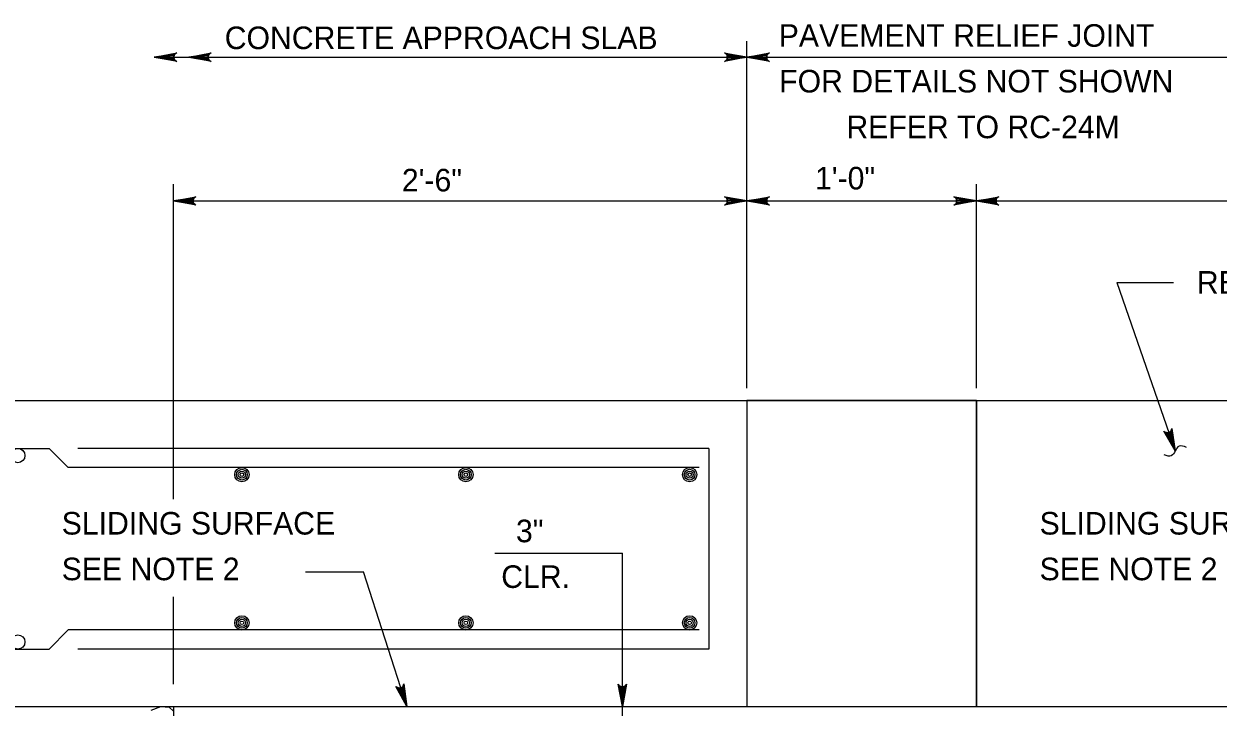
# Model space of a CAD drawing. Extents: x 638079 to 640019, y 297691 to 298879.
# Drawn here: x 639245.9 to 639404.5, y 298536.4 to 298627.2 of the extents above; entities that cross this region are included whole.
import ezdxf

# ---------------------------------------------------------------- set-up
doc = ezdxf.new("R2010")
doc.units = 0
doc.layers.add('1', color=7, linetype='Continuous')

msp = doc.modelspace()

# ---------------------------------------------------------------- linework, layer by layer
at = {"layer": '1'}
for p, q in [((639341.94, 298578.79), (639341.94, 298624.88)), ((639263.19, 298622.76), (639341.94, 298622.76)), ((639341.94, 298622.76), (639417.03, 298622.76)), ((639265.74, 298564.03), (639265.74, 298605.88)), ((639372.42, 298578.79), (639372.42, 298605.88)), ((639265.74, 298603.66), (639448.62, 298603.66)), ((639391.09, 298592.81), (639398.61, 298592.81)), ((639391.09, 298592.81), (639398.84, 298570.43)), ((639199.6, 298577.12), (639341.94, 298577.12)), ((639341.94, 298577.12), (639523.91, 298577.12)), ((639341.94, 298577.12), (639341.94, 298536.48)), ((639372.42, 298577.12), (639372.42, 298536.48)), ((639199.6, 298570.77), (639249.23, 298570.77)), ((639251.77, 298568.23), (639249.23, 298570.77)), ((639336.86, 298570.77), (639253.04, 298570.77)), ((639336.86, 298570.77), (639336.86, 298544.1)), ((639335.59, 298568.23), (639251.77, 298568.23)), ((639308.44, 298556.84), (639325.38, 298556.84)), ((639325.38, 298522.44), (639325.38, 298556.84)), ((639283.3, 298554.39), (639291.01, 298554.39)), ((639296.74, 298536.48), (639291.01, 298554.39)), ((639265.74, 298539.46), (639265.74, 298551.03)), ((639251.77, 298546.64), (639249.23, 298544.1)), ((639335.59, 298546.64), (639251.77, 298546.64)), ((639199.6, 298544.1), (639249.23, 298544.1)), ((639336.86, 298544.1), (639253.04, 298544.1)), ((639199.6, 298536.48), (639341.94, 298536.48)), ((639265.74, 298536.48), (639448.62, 298536.48)), ((639265.74, 298536.48), (639265.74, 298506))]:
    msp.add_line(p, q, dxfattribs=at)
for points in [[(639263.19, 298622.76), (639266.17, 298623.32), (639266.05, 298623.24), (639265.94, 298623.16), (639265.88, 298623.06), (639265.82, 298622.96), (639265.8, 298622.86), (639265.79, 298622.76), (639265.8, 298622.66), (639265.82, 298622.56), (639265.88, 298622.46), (639265.94, 298622.36), (639266.05, 298622.28), (639266.17, 298622.2), (639263.19, 298622.76), (639266.05, 298622.28), (639265.94, 298622.36), (639263.19, 298622.76), (639265.88, 298622.46), (639265.82, 298622.56), (639263.19, 298622.76), (639265.8, 298622.66), (639265.79, 298622.76), (639263.19, 298622.76), (639265.8, 298622.86), (639265.82, 298622.96), (639263.19, 298622.76), (639265.88, 298623.06), (639265.94, 298623.16), (639263.19, 298622.76), (639266.05, 298623.24)], [(639267.76, 298622.76), (639270.74, 298623.32), (639270.63, 298623.24), (639270.51, 298623.16), (639270.45, 298623.06), (639270.39, 298622.96), (639270.37, 298622.86), (639270.36, 298622.76), (639270.37, 298622.66), (639270.39, 298622.56), (639270.45, 298622.46), (639270.51, 298622.36), (639270.63, 298622.28), (639270.74, 298622.2), (639267.76, 298622.76), (639270.63, 298622.28), (639270.51, 298622.36), (639267.76, 298622.76), (639270.45, 298622.46), (639270.39, 298622.56), (639267.76, 298622.76), (639270.37, 298622.66), (639270.36, 298622.76), (639267.76, 298622.76), (639270.37, 298622.86), (639270.39, 298622.96), (639267.76, 298622.76), (639270.45, 298623.06), (639270.51, 298623.16), (639267.76, 298622.76), (639270.63, 298623.24)], [(639341.94, 298622.76), (639338.96, 298622.2), (639339.07, 298622.28), (639339.19, 298622.36), (639339.25, 298622.46), (639339.31, 298622.56), (639339.32, 298622.66), (639339.34, 298622.76), (639339.32, 298622.86), (639339.31, 298622.96), (639339.25, 298623.06), (639339.19, 298623.16), (639339.07, 298623.24), (639338.96, 298623.32), (639341.94, 298622.76), (639339.07, 298623.24), (639339.19, 298623.16), (639341.94, 298622.76), (639339.25, 298623.06), (639339.31, 298622.96), (639341.94, 298622.76), (639339.32, 298622.86), (639339.34, 298622.76), (639341.94, 298622.76), (639339.32, 298622.66), (639339.31, 298622.56), (639341.94, 298622.76), (639339.25, 298622.46), (639339.19, 298622.36), (639341.94, 298622.76), (639339.07, 298622.28)], [(639341.94, 298622.76), (639344.92, 298623.32), (639344.81, 298623.24), (639344.69, 298623.16), (639344.63, 298623.06), (639344.57, 298622.96), (639344.56, 298622.86), (639344.54, 298622.76), (639344.56, 298622.66), (639344.57, 298622.56), (639344.63, 298622.46), (639344.69, 298622.36), (639344.81, 298622.28), (639344.92, 298622.2), (639341.94, 298622.76), (639344.81, 298622.28), (639344.69, 298622.36), (639341.94, 298622.76), (639344.63, 298622.46), (639344.57, 298622.56), (639341.94, 298622.76), (639344.56, 298622.66), (639344.54, 298622.76), (639341.94, 298622.76), (639344.56, 298622.86), (639344.57, 298622.96), (639341.94, 298622.76), (639344.63, 298623.06), (639344.69, 298623.16), (639341.94, 298622.76), (639344.81, 298623.24)], [(639265.74, 298603.66), (639268.72, 298604.22), (639268.61, 298604.14), (639268.49, 298604.06), (639268.43, 298603.96), (639268.37, 298603.86), (639268.36, 298603.76), (639268.34, 298603.66), (639268.36, 298603.56), (639268.37, 298603.46), (639268.43, 298603.36), (639268.49, 298603.26), (639268.61, 298603.18), (639268.72, 298603.1), (639265.74, 298603.66), (639268.61, 298603.18), (639268.49, 298603.26), (639265.74, 298603.66), (639268.43, 298603.36), (639268.37, 298603.46), (639265.74, 298603.66), (639268.36, 298603.56), (639268.34, 298603.66), (639265.74, 298603.66), (639268.36, 298603.76), (639268.37, 298603.86), (639265.74, 298603.66), (639268.43, 298603.96), (639268.49, 298604.06), (639265.74, 298603.66), (639268.61, 298604.14)], [(639341.94, 298603.66), (639338.96, 298603.1), (639339.07, 298603.18), (639339.19, 298603.26), (639339.25, 298603.36), (639339.31, 298603.46), (639339.32, 298603.56), (639339.34, 298603.66), (639339.32, 298603.76), (639339.31, 298603.86), (639339.25, 298603.96), (639339.19, 298604.06), (639339.07, 298604.14), (639338.96, 298604.22), (639341.94, 298603.66), (639339.07, 298604.14), (639339.19, 298604.06), (639341.94, 298603.66), (639339.25, 298603.96), (639339.31, 298603.86), (639341.94, 298603.66), (639339.32, 298603.76), (639339.34, 298603.66), (639341.94, 298603.66), (639339.32, 298603.56), (639339.31, 298603.46), (639341.94, 298603.66), (639339.25, 298603.36), (639339.19, 298603.26), (639341.94, 298603.66), (639339.07, 298603.18)], [(639341.94, 298603.66), (639344.92, 298604.22), (639344.81, 298604.14), (639344.69, 298604.06), (639344.63, 298603.96), (639344.57, 298603.86), (639344.56, 298603.76), (639344.54, 298603.66), (639344.56, 298603.56), (639344.57, 298603.46), (639344.63, 298603.36), (639344.69, 298603.26), (639344.81, 298603.18), (639344.92, 298603.1), (639341.94, 298603.66), (639344.81, 298603.18), (639344.69, 298603.26), (639341.94, 298603.66), (639344.63, 298603.36), (639344.57, 298603.46), (639341.94, 298603.66), (639344.56, 298603.56), (639344.54, 298603.66), (639341.94, 298603.66), (639344.56, 298603.76), (639344.57, 298603.86), (639341.94, 298603.66), (639344.63, 298603.96), (639344.69, 298604.06), (639341.94, 298603.66), (639344.81, 298604.14)], [(639372.42, 298603.66), (639369.44, 298603.1), (639369.55, 298603.18), (639369.67, 298603.26), (639369.73, 298603.36), (639369.79, 298603.46), (639369.8, 298603.56), (639369.82, 298603.66), (639369.8, 298603.76), (639369.79, 298603.86), (639369.73, 298603.96), (639369.67, 298604.06), (639369.55, 298604.14), (639369.44, 298604.22), (639372.42, 298603.66), (639369.55, 298604.14), (639369.67, 298604.06), (639372.42, 298603.66), (639369.73, 298603.96), (639369.79, 298603.86), (639372.42, 298603.66), (639369.8, 298603.76), (639369.82, 298603.66), (639372.42, 298603.66), (639369.8, 298603.56), (639369.79, 298603.46), (639372.42, 298603.66), (639369.73, 298603.36), (639369.67, 298603.26), (639372.42, 298603.66), (639369.55, 298603.18)], [(639372.42, 298603.66), (639375.4, 298604.22), (639375.29, 298604.14), (639375.17, 298604.06), (639375.11, 298603.96), (639375.05, 298603.86), (639375.04, 298603.76), (639375.02, 298603.66), (639375.04, 298603.56), (639375.05, 298603.46), (639375.11, 298603.36), (639375.17, 298603.26), (639375.29, 298603.18), (639375.4, 298603.1), (639372.42, 298603.66), (639375.29, 298603.18), (639375.17, 298603.26), (639372.42, 298603.66), (639375.11, 298603.36), (639375.05, 298603.46), (639372.42, 298603.66), (639375.04, 298603.56), (639375.02, 298603.66), (639372.42, 298603.66), (639375.04, 298603.76), (639375.05, 298603.86), (639372.42, 298603.66), (639375.11, 298603.96), (639375.17, 298604.06), (639372.42, 298603.66), (639375.29, 298604.14)], [(639398.84, 298570.43), (639397.34, 298573.07), (639397.45, 298572.98), (639397.56, 298572.9), (639397.68, 298572.88), (639397.79, 298572.85), (639397.89, 298572.87), (639397.99, 298572.89), (639398.08, 298572.94), (639398.17, 298572.99), (639398.25, 298573.07), (639398.32, 298573.16), (639398.36, 298573.3), (639398.4, 298573.43), (639398.84, 298570.43), (639398.36, 298573.3), (639398.32, 298573.16), (639398.84, 298570.43), (639398.25, 298573.07), (639398.17, 298572.99), (639398.84, 298570.43), (639398.08, 298572.94), (639397.99, 298572.89), (639398.84, 298570.43), (639397.89, 298572.87), (639397.79, 298572.85), (639398.84, 298570.43), (639397.68, 298572.88), (639397.56, 298572.9), (639398.84, 298570.43), (639397.45, 298572.98)], [(639296.74, 298536.48), (639295.3, 298539.15), (639295.41, 298539.07), (639295.52, 298538.98), (639295.63, 298538.96), (639295.75, 298538.93), (639295.85, 298538.94), (639295.95, 298538.96), (639296.04, 298539.01), (639296.13, 298539.05), (639296.21, 298539.14), (639296.28, 298539.23), (639296.32, 298539.36), (639296.36, 298539.49), (639296.74, 298536.48), (639296.32, 298539.36), (639296.28, 298539.23), (639296.74, 298536.48), (639296.21, 298539.14), (639296.13, 298539.05), (639296.74, 298536.48), (639296.04, 298539.01), (639295.95, 298538.96), (639296.74, 298536.48), (639295.85, 298538.94), (639295.75, 298538.93), (639296.74, 298536.48), (639295.63, 298538.96), (639295.52, 298538.98), (639296.74, 298536.48), (639295.41, 298539.07)], [(639325.38, 298536.48), (639324.82, 298539.46), (639324.9, 298539.35), (639324.98, 298539.24), (639325.08, 298539.18), (639325.18, 298539.12), (639325.28, 298539.1), (639325.38, 298539.08), (639325.48, 298539.1), (639325.58, 298539.12), (639325.68, 298539.18), (639325.78, 298539.24), (639325.86, 298539.35), (639325.94, 298539.46), (639325.38, 298536.48), (639325.86, 298539.35), (639325.78, 298539.24), (639325.38, 298536.48), (639325.68, 298539.18), (639325.58, 298539.12), (639325.38, 298536.48), (639325.48, 298539.1), (639325.38, 298539.08), (639325.38, 298536.48), (639325.28, 298539.1), (639325.18, 298539.12), (639325.38, 298536.48), (639325.08, 298539.18), (639324.98, 298539.24), (639325.38, 298536.48), (639324.9, 298539.35)], [(639262.78, 298535.98), (639264.04, 298536.48)], [(639264.04, 298536.48), (639265.19, 298536.38), (639265.74, 298535.86)]]:
    msp.add_lwpolyline(points, dxfattribs=at)
msp.add_lwpolyline([(639341.94, 298536.48), (639372.42, 298536.48), (639372.42, 298577.12), (639341.94, 298577.12)], close=True, dxfattribs=at)
for centre, radius in [((639245.06, 298569.82), 0.952), ((639274.83, 298567.28), 0.952), ((639274.83, 298567.28), 0.714), ((639274.83, 298567.28), 0.476), ((639274.83, 298567.28), 0.238), ((639304.59, 298567.28), 0.952), ((639304.59, 298567.28), 0.714), ((639304.59, 298567.28), 0.476), ((639304.59, 298567.28), 0.238), ((639334.32, 298567.28), 0.952), ((639334.32, 298567.28), 0.714), ((639334.32, 298567.28), 0.476), ((639334.32, 298567.28), 0.238), ((639274.83, 298547.59), 0.952), ((639274.83, 298547.59), 0.714), ((639274.83, 298547.59), 0.476), ((639304.59, 298547.59), 0.952), ((639304.59, 298547.59), 0.714), ((639304.59, 298547.59), 0.476), ((639334.32, 298547.59), 0.952), ((639334.32, 298547.59), 0.714), ((639334.32, 298547.59), 0.476), ((639274.83, 298547.59), 0.238), ((639304.59, 298547.59), 0.238), ((639334.32, 298547.59), 0.238), ((639245.06, 298545.05), 0.952)]:
    msp.add_circle(centre, radius, dxfattribs=at)
msp.add_spline([(639400.33, 298570.91), (639399.36, 298571.06), (639398.32, 298569.79), (639397.38, 298569.9)], degree=3, dxfattribs=at)

# ---------------------------------------------------------------- texts
for s, p in [('CONCRETE APPROACH SLAB', (639272.55, 298623.83)), ('PAVEMENT RELIEF JOINT', (639346.16, 298624.14)), ('FOR DETAILS NOT SHOWN', (639346.22, 298618.07)), ('REFER TO RC-24M', (639355.15, 298611.99)), ('1\'-0"', (639350.98, 298605.18)), ('2\'-6"', (639296.09, 298604.92)), ('REINFORCED CONCRETE', (639401.71, 298591.33)), ('SLIDING SURFACE', (639250.89, 298559.32)), ('SLIDING SURFACE', (639380.82, 298559.32)), ('3"', (639311.25, 298558.3)), ('SEE NOTE 2', (639250.89, 298553.25)), ('SEE NOTE 2', (639380.82, 298553.25)), ('CLR.', (639309.29, 298552.23))]:
    msp.add_text(s, height=3, dxfattribs=at).set_placement(p)

doc.saveas('drawing.dxf')
